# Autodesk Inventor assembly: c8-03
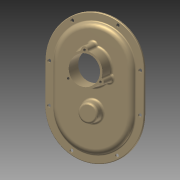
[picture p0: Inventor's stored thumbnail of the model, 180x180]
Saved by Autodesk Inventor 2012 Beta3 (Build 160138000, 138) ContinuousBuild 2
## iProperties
Created: 2010-12
Part Number: c8-03
Document SubType Name: Assembly
Designer: Beta-8540w
Author: Beta-8540w
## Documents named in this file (2)
- C:\Inventor 2012 Essentials\Assemblies\Chapter 8\c8-03.iam
- C:\Inventor 2012 Essentials\Parts\Chapter 8\c8-10.ipt
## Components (1 placed, 1 different names)
1. c8-10:1
